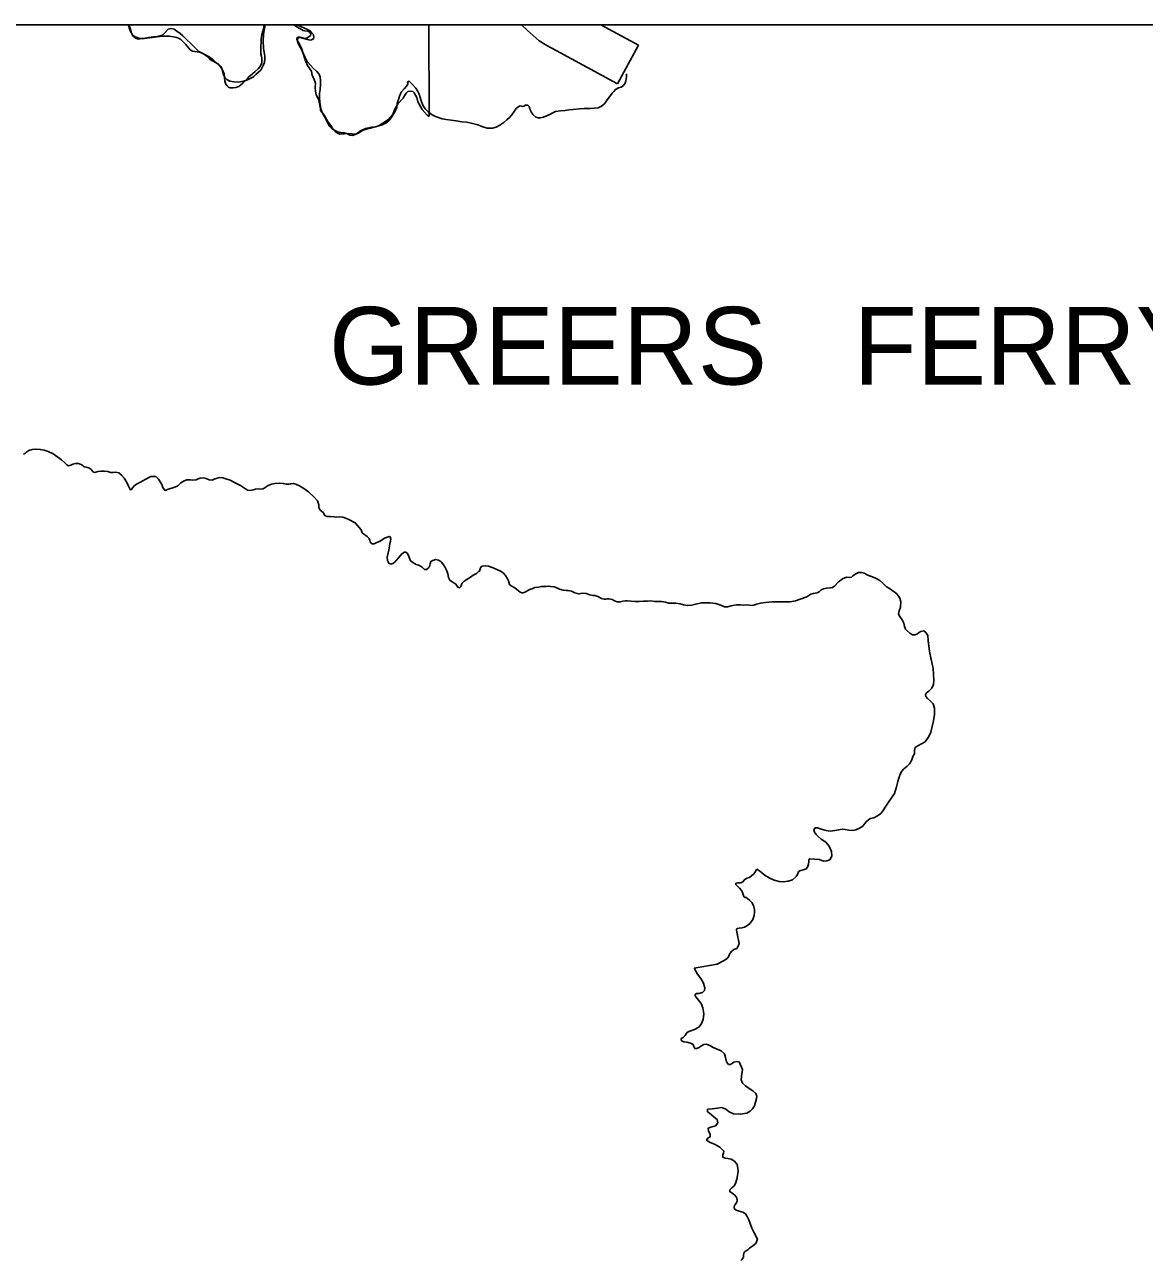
# Model space of a CAD drawing. Extents: x 1212896 to 1368412, y 378476 to 478763.
# Drawn here: x 1222895 to 1230517, y 469257 to 477661 of the extents above; entities that cross this region are included whole.
import ezdxf

# ---------------------------------------------------------------- set-up
doc = ezdxf.new("R2010")
doc.units = 0
for name, color, linetype in [('1', 7, 'Continuous'), ('Level 11', 7, 'Continuous'), ('Level 6', 7, 'Continuous'), ('Level 9', 7, 'Continuous')]:
    doc.layers.add(name, color=color, linetype=linetype)

msp = doc.modelspace()

# ---------------------------------------------------------------- linework, layer by layer
at = {"layer": '1'}
msp.add_lwpolyline([(1215273.3, 477661.4), (1246286.7, 477661.4), (1246286.7, 445613.3), (1215273.3, 445613.3)], close=True, dxfattribs=at)
at = {"layer": 'Level 11'}
for points in [[(1226276.2, 477661.4), (1226316.1, 477623.2), (1226357.5, 477588.3), (1226398.1, 477552.5), (1226449.6, 477519.9), (1226512.2, 477485.1), (1226931.6, 477258.8)], [(1226817.3, 477661.4), (1227074.1, 477522.8)], [(1227074.1, 477522.8), (1226931.6, 477258.8)]]:
    msp.add_lwpolyline(points, dxfattribs=at)
at = {"layer": 'Level 6'}
for points in [[(1224520.9, 477595.4), (1224517.3, 477548.6), (1224520.5, 477501.4), (1224527.8, 477459.4), (1224528.9, 477448.9), (1224528.9, 477433.2), (1224526.8, 477403.8), (1224519.4, 477382.8), (1224501.6, 477352.4), (1224471.2, 477324), (1224453.4, 477306.2), (1224415.6, 477288.4), (1224399.9, 477282.1), (1224374.7, 477274.7), (1224349.6, 477270.5), (1224319.2, 477271.6), (1224291.9, 477276.8), (1224271.3, 477288.9), (1224257.3, 477302.9), (1224247, 477327.9), (1224236.7, 477365.5), (1224230.8, 477376.5), (1224224.1, 477383.9), (1224213.8, 477392), (1224204.3, 477397.9), (1224182.2, 477410.4), (1224166, 477417.1), (1224152, 477428.9), (1224135.1, 477447.3), (1224106.3, 477466.4), (1224085.7, 477474.5), (1224038.1, 477480.4), (1224022.4, 477490.9), (1223992, 477525.5), (1223957.4, 477561.2), (1223942.7, 477569.6), (1223930.2, 477573.8), (1223907.1, 477579), (1223878.8, 477582.2), (1223833.7, 477584.3), (1223708.9, 477568.5), (1223681.7, 477565.4), (1223666.6, 477563.8), (1223648.1, 477571.7), (1223633.4, 477584.3), (1223622.9, 477603.1), (1223612.4, 477637.8), (1223603.6, 477661.4)], [(1224531.8, 477661.4), (1224525.3, 477622.7), (1224520.9, 477595.4)], [(1225648.5, 477035.5), (1225635.7, 477046.4), (1225600.3, 477084.8), (1225572.3, 477135.6), (1225564.2, 477166.5), (1225556.1, 477182), (1225546.6, 477197.5), (1225536.3, 477206.3), (1225517.8, 477207.8), (1225503.1, 477206.3), (1225493.5, 477198.2), (1225486.2, 477189.4), (1225470.7, 477162.1), (1225435.4, 477122.3), (1225411.8, 477081.1), (1225400.8, 477050.1), (1225371.3, 477015.5), (1225308, 476975), (1225285.9, 476965.4), (1225257.2, 476963.2), (1225214.5, 476953.6), (1225179.9, 476938.9), (1225153.4, 476918.2), (1225144.5, 476916.8), (1225098.9, 476919.7), (1225040.7, 476916), (1225025.3, 476922.7), (1225008.3, 476934.4), (1224995.8, 476947.7), (1224978.1, 476975.7), (1224961.2, 476998.5), (1224934, 477046.4), (1224909.7, 477078.1), (1224908.2, 477088.4), (1224900.1, 477133.4), (1224894.2, 477154.8), (1224879.5, 477185), (1224874.3, 477207.8), (1224872.1, 477231.4), (1224873.6, 477262.3), (1224862.5, 477294.8), (1224853, 477315.4), (1224847.1, 477345.6), (1224819.8, 477383.2), (1224804.4, 477421.5), (1224779.3, 477501.8), (1224756.5, 477544.5), (1224746.9, 477560), (1224747.7, 477570.3), (1224755.8, 477577), (1224770.5, 477575.5), (1224802.5, 477567.5), (1224817.6, 477571.8), (1224831.9, 477580.1), (1224840.3, 477588.5), (1224843.4, 477595.8), (1224838.2, 477608.7), (1224823.5, 477618.2), (1224802.9, 477620.4), (1224790.4, 477622.7), (1224741, 477652.1), (1224728, 477661.4)], [(1225645.6, 477661.4), (1225648.5, 477035.5)]]:
    msp.add_lwpolyline(points, dxfattribs=at)
at = {"layer": 'Level 9'}
for points in [[(1224528.5, 477661.4), (1224523.2, 477644.6), (1224515, 477618.2), (1224508.8, 477594), (1224504.7, 477563.8), (1224504.5, 477540.7), (1224503.2, 477516.6), (1224501.8, 477496.5), (1224501.6, 477473.4), (1224502.9, 477462.4), (1224506.4, 477446.5), (1224509.8, 477433.6), (1224510.3, 477419.6), (1224508.8, 477402.5), (1224498.6, 477377.1), (1224485.1, 477361.6), (1224464.6, 477342.9), (1224445.1, 477326.3), (1224420.8, 477305.5), (1224409.1, 477293.1), (1224394.6, 477277.6), (1224381, 477264.2), (1224364.5, 477248.6), (1224351.7, 477240.2), (1224332.9, 477234.6), (1224314, 477231), (1224294, 477231.4), (1224282.8, 477236.1), (1224272.5, 477245.8), (1224265.1, 477256.6), (1224258.5, 477276.4), (1224254.7, 477302.4), (1224251.9, 477327.4), (1224241, 477355.1), (1224225.3, 477377.7), (1224203.6, 477399.1), (1224176.9, 477421.3), (1224150.2, 477441.6), (1224108.4, 477464.4), (1224079.9, 477479.5), (1224056.2, 477502.9), (1224024.1, 477535), (1223999.3, 477559.3), (1223972.5, 477584.5), (1223953, 477601), (1223931.5, 477616.4), (1223913, 477629.8), (1223891.8, 477636.2), (1223871, 477630.6), (1223851.6, 477607.9), (1223832.2, 477589.3), (1223798.4, 477581.2), (1223772.5, 477578.4), (1223738.6, 477574.3), (1223714.7, 477569.6), (1223677.7, 477567.5), (1223647.3, 477578.6), (1223626.8, 477596), (1223615.1, 477615.7), (1223609.6, 477633.6), (1223601.9, 477656.4), (1223599.8, 477661.4)], [(1224818.9, 477411), (1224804, 477438.6), (1224785.8, 477477.1), (1224770.7, 477508.8), (1224759.1, 477529.5), (1224752.5, 477548.3), (1224752, 477562.4), (1224756.7, 477574.5), (1224769.7, 477574.9), (1224795.9, 477567.7), (1224820.2, 477560.4), (1224837.3, 477556.9), (1224848.3, 477558.3), (1224860, 477565.7), (1224863.7, 477577.8), (1224859.1, 477596.7), (1224841.4, 477616.2), (1224821, 477628.6), (1224800.7, 477638.1), (1224775.4, 477648.3), (1224750, 477659.6), (1224746.5, 477661.4)], [(1226823.1, 477661.4), (1226822.4, 477658.5)], [(1226390.6, 477027.1), (1226374.5, 477031.6), (1226353.9, 477049), (1226343.3, 477067.7), (1226336.8, 477081.6), (1226333.5, 477091.5), (1226331.3, 477097.4), (1226328.1, 477104.4), (1226320.8, 477113.2), (1226304.8, 477113.7), (1226294, 477106.3), (1226286.1, 477104.1), (1226278, 477107.8), (1226267.9, 477108.5), (1226259, 477105.2), (1226240.4, 477091.6), (1226228.1, 477071.2), (1226210.7, 477048.6), (1226196.3, 477030.1), (1226176.8, 477013.5), (1226156.3, 476995.8), (1226128.9, 476976.9), (1226105.3, 476964.1), (1226080.5, 476957.4), (1226043.4, 476957.2), (1226014.2, 476965.4), (1225980.7, 476979.4), (1225942.3, 476989.2), (1225905, 476997.1), (1225869.9, 477001), (1225831.7, 477005.9), (1225797.5, 477011.9), (1225764.3, 477015.8), (1225736.1, 477020), (1225691.6, 477035.7), (1225669.2, 477047), (1225641.5, 477068.2), (1225620.8, 477089.7), (1225608.2, 477108.3), (1225595.3, 477136), (1225587.4, 477164.8), (1225580.7, 477188.7), (1225568.9, 477211.4), (1225557.3, 477230.1), (1225533.5, 477256.4), (1225524.2, 477265.2), (1225519, 477271), (1225513.9, 477274.9), (1225511.9, 477275.8), (1225502, 477271.5), (1225503.2, 477265.5), (1225503.4, 477257.5), (1225494.9, 477242.2), (1225477.4, 477225.6), (1225459, 477205), (1225449.7, 477182.7), (1225441.5, 477158.4), (1225431.5, 477124), (1225427.4, 477097.8), (1225415.3, 477067.3), (1225390.5, 477027.4), (1225375.1, 477008.9), (1225354.6, 476992.2), (1225327.9, 476980.4), (1225298.2, 476971.4), (1225271.4, 476964.6), (1225248.6, 476957.9), (1225235.6, 476955.5), (1225213.8, 476948.8), (1225194.1, 476940.2), (1225181.3, 476932.8), (1225177.4, 476929.6), (1225171.5, 476924.4), (1225156.7, 476918), (1225140.9, 476911.5), (1225129, 476907.1), (1225108.9, 476909.5), (1225093.6, 476919), (1225070.4, 476925.3), (1225047.3, 476927.6), (1225025.1, 476933), (1225003.8, 476943.3), (1224985.4, 476953.8), (1224967.8, 476973.3), (1224952.8, 477004), (1224943.2, 477021.7), (1224934.8, 477036.5), (1224922, 477060.2), (1224911.1, 477087.9), (1224903.7, 477133.8), (1224900.8, 477162.8), (1224902.8, 477192.9), (1224906, 477220.1), (1224908.9, 477253.3), (1224909, 477281.4), (1224907.3, 477303.4), (1224898.7, 477324.2), (1224883.1, 477342.8), (1224859.4, 477365.1), (1224837.6, 477387.5), (1224818.9, 477411)], [(1226992.6, 477325.9), (1226992.5, 477305.3), (1226988.3, 477280.1), (1226981.8, 477262.8), (1226971.3, 477246.5), (1226954.7, 477235.9), (1226936.7, 477232.4), (1226917.1, 477220.7), (1226904.5, 477207.3), (1226893.9, 477194.9), (1226855.5, 477142.6), (1226841.1, 477123.1), (1226820.6, 477106.5), (1226797.9, 477095.7), (1226771.9, 477093.9), (1226747, 477091.2), (1226704, 477089.8), (1226671, 477087.8), (1226628.1, 477084.5), (1226601.2, 477080.7), (1226574.2, 477077.8), (1226542.2, 477075.8), (1226509.4, 477070.8), (1226489.6, 477062.2), (1226469, 477050.5), (1226443.3, 477039.7), (1226426.5, 477032.2), (1226404.7, 477026.5), (1226390.6, 477027.1)], [(1224328.5, 474543), (1224293.9, 474560), (1224263.6, 474569.1), (1224243.4, 474575.5), (1224223.3, 474578.9), (1224205.4, 474574.3), (1224185.6, 474566.7), (1224170.8, 474561.2), (1224151.7, 474562.7), (1224130.4, 474571), (1224111.3, 474575.5), (1224090.3, 474573.8), (1224075.4, 474570.3), (1224061.6, 474563.9), (1224038.6, 474561.2), (1224022.6, 474562.7), (1223998.5, 474563), (1223979.7, 474556.4), (1223958.1, 474542.7), (1223943.5, 474529.2), (1223935.8, 474519.9), (1223896.2, 474505.7), (1223872.4, 474498.9), (1223850.6, 474491.2), (1223837.1, 474506.9), (1223826.2, 474535.6), (1223806.2, 474568.1), (1223787.6, 474584.6), (1223754.6, 474584.6), (1223714.2, 474564.3), (1223682.7, 474546.3), (1223657.1, 474534.4), (1223638.5, 474518.8), (1223627, 474503.4), (1223623.2, 474497.3), (1223616.3, 474494.1), (1223610.1, 474500.9), (1223601.5, 474519.7), (1223587.5, 474549.3), (1223571.7, 474573.9), (1223553, 474595.4), (1223535.6, 474609.9), (1223514.4, 474614.3), (1223497.4, 474612.8), (1223478.4, 474613.2), (1223461.1, 474620.7), (1223436, 474622.9), (1223414, 474622.2), (1223392.1, 474619.6), (1223372.3, 474613.9), (1223363.2, 474615.7), (1223346.6, 474633.2), (1223335.3, 474642.9), (1223314.1, 474649.2), (1223300, 474651.8), (1223283.6, 474664.4), (1223261.2, 474674.7), (1223241.2, 474675.1), (1223222.3, 474670.5), (1223209.6, 474662.1), (1223192.7, 474658.6), (1223181.4, 474665.2), (1223165.9, 474681.8), (1223145.3, 474700.2), (1223089, 474740.6), (1223054.4, 474756.6), (1223028.1, 474764.8), (1223001, 474770), (1222967.9, 474772), (1222946, 474768.3), (1222923.1, 474761.6), (1222910.4, 474753.2), (1222899.6, 474744.8), (1222887.8, 474738.4)], [(1225873.6, 473860.5), (1225868.9, 473850.3), (1225863.3, 473837.1), (1225854.6, 473828.8), (1225842.5, 473831.4), (1225830.8, 473853.1), (1225816.6, 473860.7), (1225804.3, 473868.4), (1225789.9, 473880), (1225780.4, 473897.7), (1225775.5, 473923.6), (1225765.8, 473947.4), (1225754, 473971.1), (1225741.4, 473991.8), (1225728.9, 474006.4), (1225711.5, 474016.9), (1225691.4, 474020.3), (1225672.6, 474014.7), (1225660.8, 474007.4), (1225656.3, 473990.2), (1225649.8, 473973.9), (1225639.3, 473959.6), (1225629.5, 473952.2), (1225616.4, 473952.8), (1225602, 473965.4), (1225581.6, 473978.8), (1225559.3, 473987.2), (1225530.7, 474004.4), (1225522.5, 474012.1), (1225514.9, 474029.9), (1225508.3, 474048.8), (1225497.8, 474063.5), (1225489.6, 474070.3), (1225480.6, 474071), (1225463, 474058.4), (1225441.7, 474033.7), (1225426.2, 474016.2), (1225414.7, 474001.8), (1225402, 473992.4), (1225388, 473989.9), (1225372.8, 473996.5), (1225364.3, 474013.3), (1225363.5, 474037.3), (1225374.1, 474083.8), (1225381.6, 474130.1), (1225385.2, 474144.3), (1225386.7, 474158.4), (1225383.2, 474174.3), (1225375.1, 474178.1), (1225343.5, 474165.1), (1225315, 474146.1), (1225288.4, 474133.3), (1225274.6, 474127.9), (1225259.6, 474127.4), (1225247.2, 474138), (1225244.8, 474153), (1225240.4, 474163.9), (1225227, 474176.5), (1225216.7, 474184.2), (1225204.5, 474192.9), (1225193.1, 474202.6), (1225186.5, 474223.4), (1225145, 474270.3), (1225096.1, 474294.9), (1225060.6, 474309.8), (1225036.5, 474312.1), (1225019.6, 474308.5), (1225000.6, 474310), (1224974.4, 474314.2), (1224954.4, 474313.6), (1224938.2, 474320.1), (1224926.5, 474339.8), (1224907, 474357.2), (1224898.4, 474374), (1224897.9, 474392), (1224889, 474418.9), (1224864.1, 474447.2), (1224826, 474480.1), (1224796.3, 474503.2), (1224766.7, 474521.4), (1224740.2, 474533.6), (1224724.1, 474537.1), (1224706.1, 474536.6), (1224695.2, 474534.2), (1224677.2, 474532.7), (1224655, 474538), (1224631.9, 474541.3), (1224597, 474537.2), (1224576.1, 474533.6), (1224553.3, 474524.9), (1224531.7, 474511.2), (1224518, 474502.7), (1224506, 474500.3), (1224484, 474500.7), (1224467, 474500.1), (1224451.1, 474495.6), (1224429.3, 474491), (1224412.2, 474492.4), (1224390.7, 474506.8), (1224363.1, 474525), (1224328.5, 474543)], [(1227876.3, 473716.4), (1227859.5, 473709.9), (1227842.5, 473708.4), (1227811.3, 473712.4), (1227791.4, 473710.8), (1227768.3, 473711.1), (1227740.3, 473711.2), (1227716.4, 473708.5), (1227704.5, 473705.1), (1227678.6, 473699.3), (1227659.6, 473698.7), (1227634.3, 473709), (1227598.9, 473719.9), (1227559.7, 473724.7), (1227525.6, 473725.7), (1227501.6, 473725), (1227472.8, 473719.1), (1227462.8, 473716.7), (1227436.1, 473708.9), (1227406.1, 473707), (1227378.9, 473712.2), (1227356.6, 473719.5), (1227326.5, 473723.6), (1227307.4, 473724), (1227280.4, 473724.2), (1227256.2, 473729.5), (1227231.1, 473733.7), (1227206, 473733.9), (1227185, 473734.3), (1227154.8, 473738.4), (1227135.8, 473737.8), (1227104.9, 473735.8), (1227078.9, 473735), (1227051.8, 473735.2), (1227023.7, 473737.4), (1226998.6, 473739.6), (1226982.6, 473739.1), (1226966.7, 473736.6), (1226948.8, 473732), (1226928.8, 473731.4), (1226909.6, 473738.9), (1226893.3, 473747.4), (1226871.1, 473752.7), (1226859.1, 473752.3), (1226850.1, 473751.1), (1226840.1, 473750.8), (1226820.9, 473755.2), (1226795.5, 473769.4), (1226777.2, 473775.9), (1226763.2, 473776.5), (1226742.1, 473780.8), (1226717.8, 473789.1), (1226694.7, 473790.4), (1226679.7, 473789), (1226666.8, 473786.6), (1226640.6, 473792.8), (1226617.2, 473805.1), (1226594, 473808.4), (1226581, 473810), (1226559.9, 473811.3), (1226536.6, 473818.7), (1226517.3, 473828.1), (1226500.1, 473833.6), (1226475, 473837.8), (1226457.9, 473839.3), (1226443, 473836.8), (1226414, 473835.9), (1226392, 473833.3), (1226368.1, 473829.5), (1226350.4, 473821), (1226338.5, 473817.6), (1226323.6, 473812.1), (1226307.9, 473802.6), (1226296.1, 473795.2), (1226287.2, 473792.9), (1226279.2, 473792.7), (1226268, 473797.4), (1226257.7, 473808.1), (1226232, 473828.4), (1226205.6, 473841.6), (1226195.3, 473850.3), (1226187.5, 473875.1), (1226179.9, 473892.9), (1226167.3, 473911.6), (1226151.8, 473929.2), (1226134.4, 473940.7), (1226108, 473951.9), (1226083.6, 473963.2), (1226053.2, 473974.3), (1226031.1, 473977.6), (1226013.1, 473976.1), (1226003.2, 473972.7), (1225996.7, 473957.5), (1225991.2, 473940.3), (1225985.3, 473938.1), (1225969.7, 473924.6), (1225948.1, 473912.9), (1225929.4, 473900.3), (1225910.7, 473889.7), (1225886.2, 473872.9), (1225873.6, 473860.5)], [(1228675.8, 472262.9), (1228700.5, 472275.7), (1228722, 472292.4), (1228738.4, 472311.9), (1228751.7, 472333.4), (1228775.6, 472368.2), (1228815.8, 472427.6), (1228829.4, 472473.2), (1228838.3, 472509.5), (1228845.5, 472532.8), (1228853.7, 472560.1), (1228865.1, 472580.6), (1228880.6, 472596.1), (1228901.1, 472611.7), (1228918.6, 472629.3), (1228929, 472647.7), (1228936.5, 472663), (1228942, 472680.2), (1228951.5, 472697.5), (1228952.8, 472720.6), (1228957.1, 472741.8), (1228974.8, 472751.4), (1229024, 472780), (1229050.9, 472814.9), (1229063, 472844.3), (1229072.8, 472883.8), (1229081.5, 472923.1), (1229089.2, 472966.5), (1229088.9, 473007.6), (1229078.9, 473037.4), (1229060.3, 473055.8), (1229039.7, 473074.3), (1229029.3, 473087), (1229026.9, 473098.9), (1229033.5, 473112.2), (1229050.2, 473124.7), (1229070.6, 473144.4), (1229081.8, 473168.8), (1229084.9, 473197), (1229078.3, 473279), (1229065.4, 473339.8), (1229054.7, 473393.6), (1229046.3, 473468.6), (1229042.3, 473502.5), (1229029.6, 473524.2), (1229015.2, 473534.8), (1228995.3, 473530.2), (1228978.6, 473521.6), (1228967.8, 473513.3), (1228956, 473506.9), (1228939, 473507.4), (1228919.6, 473519.8), (1228899, 473537.2), (1228890.7, 473546), (1228885.2, 473563.9), (1228879.4, 473586.8), (1228868.7, 473609.5), (1228853, 473632.1), (1228844.5, 473647.9), (1228848.7, 473672.1), (1228857, 473695.4), (1228859.8, 473732.6), (1228853, 473758.4), (1228831.1, 473787.9), (1228790, 473819.7), (1228758.4, 473837.8), (1228735.7, 473859.1), (1228716.2, 473876.6), (1228691.6, 473891.9), (1228665.3, 473902.1), (1228638.9, 473912.3), (1228610.5, 473926.5), (1228591.3, 473932.9), (1228570.2, 473932.3), (1228548.6, 473921.6), (1228531.9, 473909), (1228524.2, 473899.8), (1228511.3, 473897.4), (1228490.2, 473899.7), (1228461.5, 473888.8), (1228433.2, 473865.9), (1228408.9, 473842.1), (1228393.3, 473830.6), (1228378.3, 473827.1), (1228354.3, 473826.4), (1228332.5, 473821.7), (1228317.7, 473814.2), (1228303.1, 473800.7), (1228289.3, 473794.3), (1228263.4, 473789.5), (1228245.6, 473783.9), (1228220.1, 473767.1), (1228174.6, 473749.6), (1228142.9, 473738.6), (1228106, 473733.5), (1228065, 473733.2), (1228031.9, 473733.2), (1227982.9, 473731.7), (1227937, 473727.3), (1227905.1, 473723.3), (1227876.3, 473716.4)], [(1227451.6, 471239.3), (1227608, 471266.4), (1227652.4, 471287.8), (1227677.9, 471304.7), (1227688.4, 471320), (1227695.9, 471337.3), (1227709.4, 471354.8), (1227722.1, 471365.2), (1227741.8, 471372.8), (1227752.4, 471388.2), (1227757.8, 471407.4), (1227754.1, 471429.3), (1227749.5, 471446.2), (1227748, 471464.2), (1227742.4, 471483.1), (1227740.8, 471501.1), (1227744.6, 471508.3), (1227759.5, 471509.7), (1227777.5, 471512.3), (1227795.3, 471517.8), (1227816, 471528.5), (1227832.5, 471544.1), (1227850.8, 471569.7), (1227860.9, 471596.1), (1227864.2, 471620.2), (1227863.6, 471638.3), (1227855.8, 471664.1), (1227845.1, 471684.8), (1227831.7, 471699.5), (1227814.2, 471714), (1227807, 471718.8), (1227799, 471719.5), (1227789.8, 471726.3), (1227784.1, 471746.1), (1227776.6, 471764), (1227762, 471782.6), (1227748.6, 471794.2), (1227735.1, 471807.8), (1227735.9, 471816.9), (1227750.8, 471819.3), (1227770.8, 471818.9), (1227784.6, 471825.4), (1227794.2, 471840.7), (1227809.9, 471850.2), (1227828.7, 471856.8), (1227843.4, 471866.3), (1227856.1, 471877.7), (1227866.6, 471893.1), (1227872.3, 471904.3), (1227880, 471911.5), (1227896.4, 471901), (1227935.4, 471870.1), (1227963, 471852.9), (1227996.5, 471836.9), (1228031.8, 471827.9), (1228060.9, 471825.8), (1228091.8, 471829.8), (1228122.6, 471838.8), (1228146.9, 471861.6), (1228155.4, 471876.9), (1228161.9, 471894.1), (1228171.7, 471901.4), (1228193.5, 471907.1), (1228215.3, 471915.8), (1228223, 471925.1), (1228231.4, 471945.4), (1228231.9, 471961.4), (1228232.4, 471974.5), (1228237.2, 471983.7), (1228305.4, 471977.7), (1228332.8, 471967.6), (1228355.8, 471968.3), (1228375.5, 471975.9), (1228389.8, 472001.4), (1228387.8, 472032.4), (1228371.6, 472068), (1228347.8, 472095.4), (1228317.1, 472116.5), (1228295.5, 472133.9), (1228282, 472149.5), (1228271.5, 472164.2), (1228268, 472180.2), (1228276.6, 472194.5), (1228291.6, 472194.9), (1228316.9, 472184.7), (1228350.3, 472174.7), (1228377.4, 472171.5), (1228409.3, 472176.5), (1228437.2, 472181.3), (1228459.1, 472184), (1228480.2, 472182.7), (1228505.3, 472178.4), (1228530.4, 472176.2), (1228553.3, 472180.9), (1228577, 472191.7), (1228599.6, 472205.4), (1228615, 472222.9), (1228626.6, 472237.3), (1228641.2, 472250.8), (1228653, 472257.2), (1228675.8, 472262.9)], [(1227468.8, 471066.3), (1227483.8, 471065.7), (1227508.6, 471072.3), (1227522.3, 471085.6), (1227524.8, 471105.7), (1227515.1, 471136.6), (1227498.3, 471167.2), (1227475.5, 471198.7), (1227451.6, 471239.3)], [(1227696.2, 469730.1), (1227708.9, 469742.4), (1227725.6, 469756.8), (1227734.2, 469773), (1227742.5, 469802.3), (1227747.9, 469827.5), (1227751.2, 469854.6), (1227750.7, 469877.6), (1227745.1, 469902.5), (1227726.5, 469924.1), (1227705.2, 469937.7), (1227681.1, 469943.1), (1227663, 469945.7), (1227647.8, 469951.4), (1227647.5, 469967.4), (1227652.2, 469978.5), (1227653.9, 469991.6), (1227628.2, 470019), (1227595.7, 470038.3), (1227562.4, 470052.5), (1227537, 470068), (1227545.6, 470082.2), (1227560.5, 470089.6), (1227562, 470106.6), (1227549.5, 470130.4), (1227548, 470148.4), (1227566.8, 470156.9), (1227596.6, 470165.6), (1227613.1, 470186), (1227608.6, 470208.9), (1227588.2, 470223.5), (1227569.8, 470240.1), (1227556.6, 470250.8), (1227544.3, 470261.5), (1227543.9, 470277.6), (1227574.8, 470281.3), (1227611.7, 470286.2), (1227640.6, 470289.8), (1227667.9, 470278.5), (1227691.4, 470260), (1227720.7, 470246.6), (1227765.8, 470243.7), (1227810.6, 470251.8), (1227833.3, 470264.3), (1227849.9, 470281.7), (1227862.4, 470302.1), (1227870.9, 470326.3), (1227877.3, 470351.5), (1227878.9, 470367.6), (1227871.5, 470384.4), (1227852, 470403), (1227826.6, 470419.5), (1227802.1, 470437.9), (1227780.7, 470455.5), (1227772.2, 470477.3), (1227777.1, 470521.5), (1227778.8, 470532.6), (1227782.4, 470549.7), (1227758.2, 470600.2), (1227743.1, 470602.9), (1227722.2, 470599.4), (1227713.4, 470592.1), (1227700.5, 470583.8), (1227686.6, 470582.5), (1227672.1, 470600.2), (1227666.4, 470631.1), (1227659.8, 470655), (1227636.3, 470675.5), (1227608, 470687.9), (1227580.7, 470698.2), (1227563.4, 470710.9), (1227537.1, 470721.3), (1227519.2, 470719.8), (1227497.4, 470708.3), (1227485.7, 470699), (1227467.8, 470691.6), (1227457.8, 470692.3), (1227450.5, 470704.2), (1227445.2, 470718.1), (1227426.9, 470728.7), (1227402.8, 470734.1), (1227382.7, 470736.7), (1227364.5, 470746.3), (1227363.1, 470759.3), (1227377.9, 470767.6), (1227391.7, 470780), (1227398.4, 470792.1), (1227404.1, 470801.3), (1227416, 470807.6), (1227455.7, 470820.5), (1227483.3, 470837.2), (1227500.8, 470857.7), (1227513, 470890), (1227518.1, 470928.2), (1227511.1, 470969.1), (1227500.4, 470996.9), (1227482.8, 471021.6), (1227472.6, 471032.4), (1227459.2, 471049.1), (1227459.9, 471060.1), (1227468.8, 471066.3)], [(1227770.9, 469248.9), (1227779.7, 469257.1), (1227788.4, 469270.3), (1227789.1, 469284.4), (1227792.6, 469304.5), (1227805.3, 469314.8), (1227818.2, 469322.1), (1227830, 469331.4), (1227851.5, 469349), (1227871.2, 469364.4), (1227882.5, 469393.8), (1227859.3, 469442.3), (1227845.6, 469469.1), (1227833.8, 469500.8), (1227824.2, 469525.7), (1227813.7, 469548.5), (1227802.3, 469566.2), (1227783, 469576.8), (1227758.8, 469585.2), (1227738.6, 469590.8), (1227725.3, 469603.5), (1227725, 469616.5), (1227731.7, 469628.7), (1227740.4, 469641.9), (1227746.1, 469654.1), (1227742.6, 469676), (1227730.1, 469693.8), (1227711.8, 469706.4), (1227694.5, 469717), (1227696.2, 469730.1)]]:
    msp.add_lwpolyline(points, dxfattribs=at)

# ---------------------------------------------------------------- texts
msp.add_text('GREERS   FERRY   LAKE', height=527.999, dxfattribs=at).set_placement((1224966.3, 475211.7))

doc.saveas('drawing.dxf')
